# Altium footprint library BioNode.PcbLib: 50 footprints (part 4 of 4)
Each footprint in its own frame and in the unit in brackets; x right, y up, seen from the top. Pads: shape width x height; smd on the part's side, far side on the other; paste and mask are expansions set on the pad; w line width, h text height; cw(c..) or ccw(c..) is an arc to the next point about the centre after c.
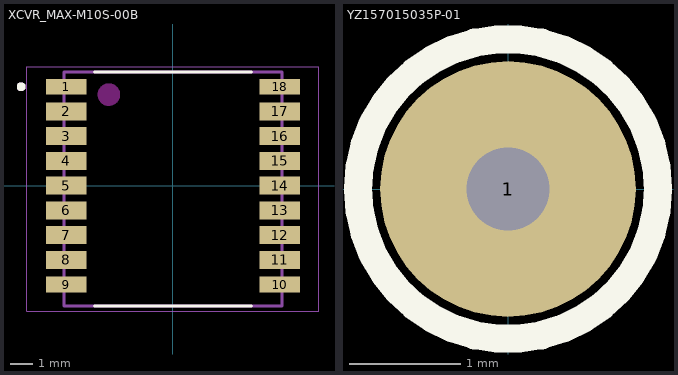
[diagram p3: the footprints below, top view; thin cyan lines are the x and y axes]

## XCVR_MAX-M10S-00B [mm]
height 2.7
pads (18):
  rect 1.8x0.7 smd paste-2: 1(-4.75,4.4) 9(-4.75,-4.4) 10(4.75,-4.4) 18(4.75,4.4)
  rect 1.8x0.8 smd paste-2: 2(-4.75,3.3) 3(-4.75,2.2) 4(-4.75,1.1) 5(-4.75,0) 6(-4.75,-1.1) 7(-4.75,-2.2) 8(-4.75,-3.3) 11(4.75,-3.3) 12(4.75,-2.2) 13(4.75,-1.1) 14(4.75,0) 15(4.75,1.1) 16(4.75,2.2) 17(4.75,3.3)
Top Overlay:
  circle w0.2: c-6.75,4.4 r0.1
  lines w0.127: -3.49,-5.35 3.49,-5.35 ; -3.49,5.05 3.49,5.05
Top Paste:
  region: -4.85,0.3 -3.95,0.3 -3.95,-0.3 -4.85,-0.3 -4.85,-0.4 -6.25,-0.4 -6.25,0.4 -4.85,0.4
  region: -4.85,4.65 -3.95,4.65 -3.95,4.15 -4.85,4.15 -4.85,4.05 -6.25,4.05 -6.25,4.75 -4.85,4.75
  region: 6.25,4.05 4.85,4.05 4.85,4.15 3.95,4.15 3.95,4.65 4.85,4.65 4.85,4.75 6.25,4.75
  region: -4.85,3.6 -3.95,3.6 -3.95,3 -4.85,3 -4.85,2.9 -6.25,2.9 -6.25,3.7 -4.85,3.7
  region: -4.85,2.5 -3.95,2.5 -3.95,1.9 -4.85,1.9 -4.85,1.8 -6.25,1.8 -6.25,2.6 -4.85,2.6
  region: -4.85,1.4 -3.95,1.4 -3.95,0.8 -4.85,0.8 -4.85,0.7 -6.25,0.7 -6.25,1.5 -4.85,1.5
  region: -4.85,-0.8 -3.95,-0.8 -3.95,-1.4 -4.85,-1.4 -4.85,-1.5 -6.25,-1.5 -6.25,-0.7 -4.85,-0.7
  region: -4.85,-1.9 -3.95,-1.9 -3.95,-2.5 -4.85,-2.5 -4.85,-2.6 -6.25,-2.6 -6.25,-1.8 -4.85,-1.8
  region: -4.85,-3 -3.95,-3 -3.95,-3.6 -4.85,-3.6 -4.85,-3.7 -6.25,-3.7 -6.25,-2.9 -4.85,-2.9
  region: 6.25,-0.4 4.85,-0.4 4.85,-0.3 3.95,-0.3 3.95,0.3 4.85,0.3 4.85,0.4 6.25,0.4
  region: 6.25,2.9 4.85,2.9 4.85,3 3.95,3 3.95,3.6 4.85,3.6 4.85,3.7 6.25,3.7
  region: 6.25,1.8 4.85,1.8 4.85,1.9 3.95,1.9 3.95,2.5 4.85,2.5 4.85,2.6 6.25,2.6
  region: 6.25,0.7 4.85,0.7 4.85,0.8 3.95,0.8 3.95,1.4 4.85,1.4 4.85,1.5 6.25,1.5
  region: 6.25,-1.5 4.85,-1.5 4.85,-1.4 3.95,-1.4 3.95,-0.8 4.85,-0.8 4.85,-0.7 6.25,-0.7
  region: 6.25,-2.6 4.85,-2.6 4.85,-2.5 3.95,-2.5 3.95,-1.9 4.85,-1.9 4.85,-1.8 6.25,-1.8
  region: 6.25,-3.7 4.85,-3.7 4.85,-3.6 3.95,-3.6 3.95,-3 4.85,-3 4.85,-2.9 6.25,-2.9
  region: -4.85,-4.15 -3.95,-4.15 -3.95,-4.65 -4.85,-4.65 -4.85,-4.75 -6.25,-4.75 -6.25,-4.05 -4.85,-4.05
  region: 6.25,-4.75 4.85,-4.75 4.85,-4.65 3.95,-4.65 3.95,-4.15 4.85,-4.15 4.85,-4.05 6.25,-4.05
Keep-Out Layer:
  circle w0.5: c-2.85,4.05 r0.25
Mechanical 13:
  circle w0.2: c-6.75,4.4 r0.1
  lines w0.127: -4.85,-5.35 4.85,-5.35 4.85,5.05 -4.85,5.05 -4.85,-5.35
Mechanical 15:
  lines w0.05: -6.5,-5.6 6.5,-5.6 6.5,5.3 -6.5,5.3 -6.5,-5.6
3D body "step_temp.STEP": height 2.7, standoff 0, extent -4.85,-5.35 4.85,5.05

## YZ157015035P-01 [mm]
pads (1):
  rrect100% 2.3x2.3 hole 0.75: 1(0,0)
Top Overlay:
  circle w0.254: c0,0 r1.35
3D body "YZ157015035P-01.step": height 3.02, standoff -0.48, extent -1,-0.993 1,0.993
